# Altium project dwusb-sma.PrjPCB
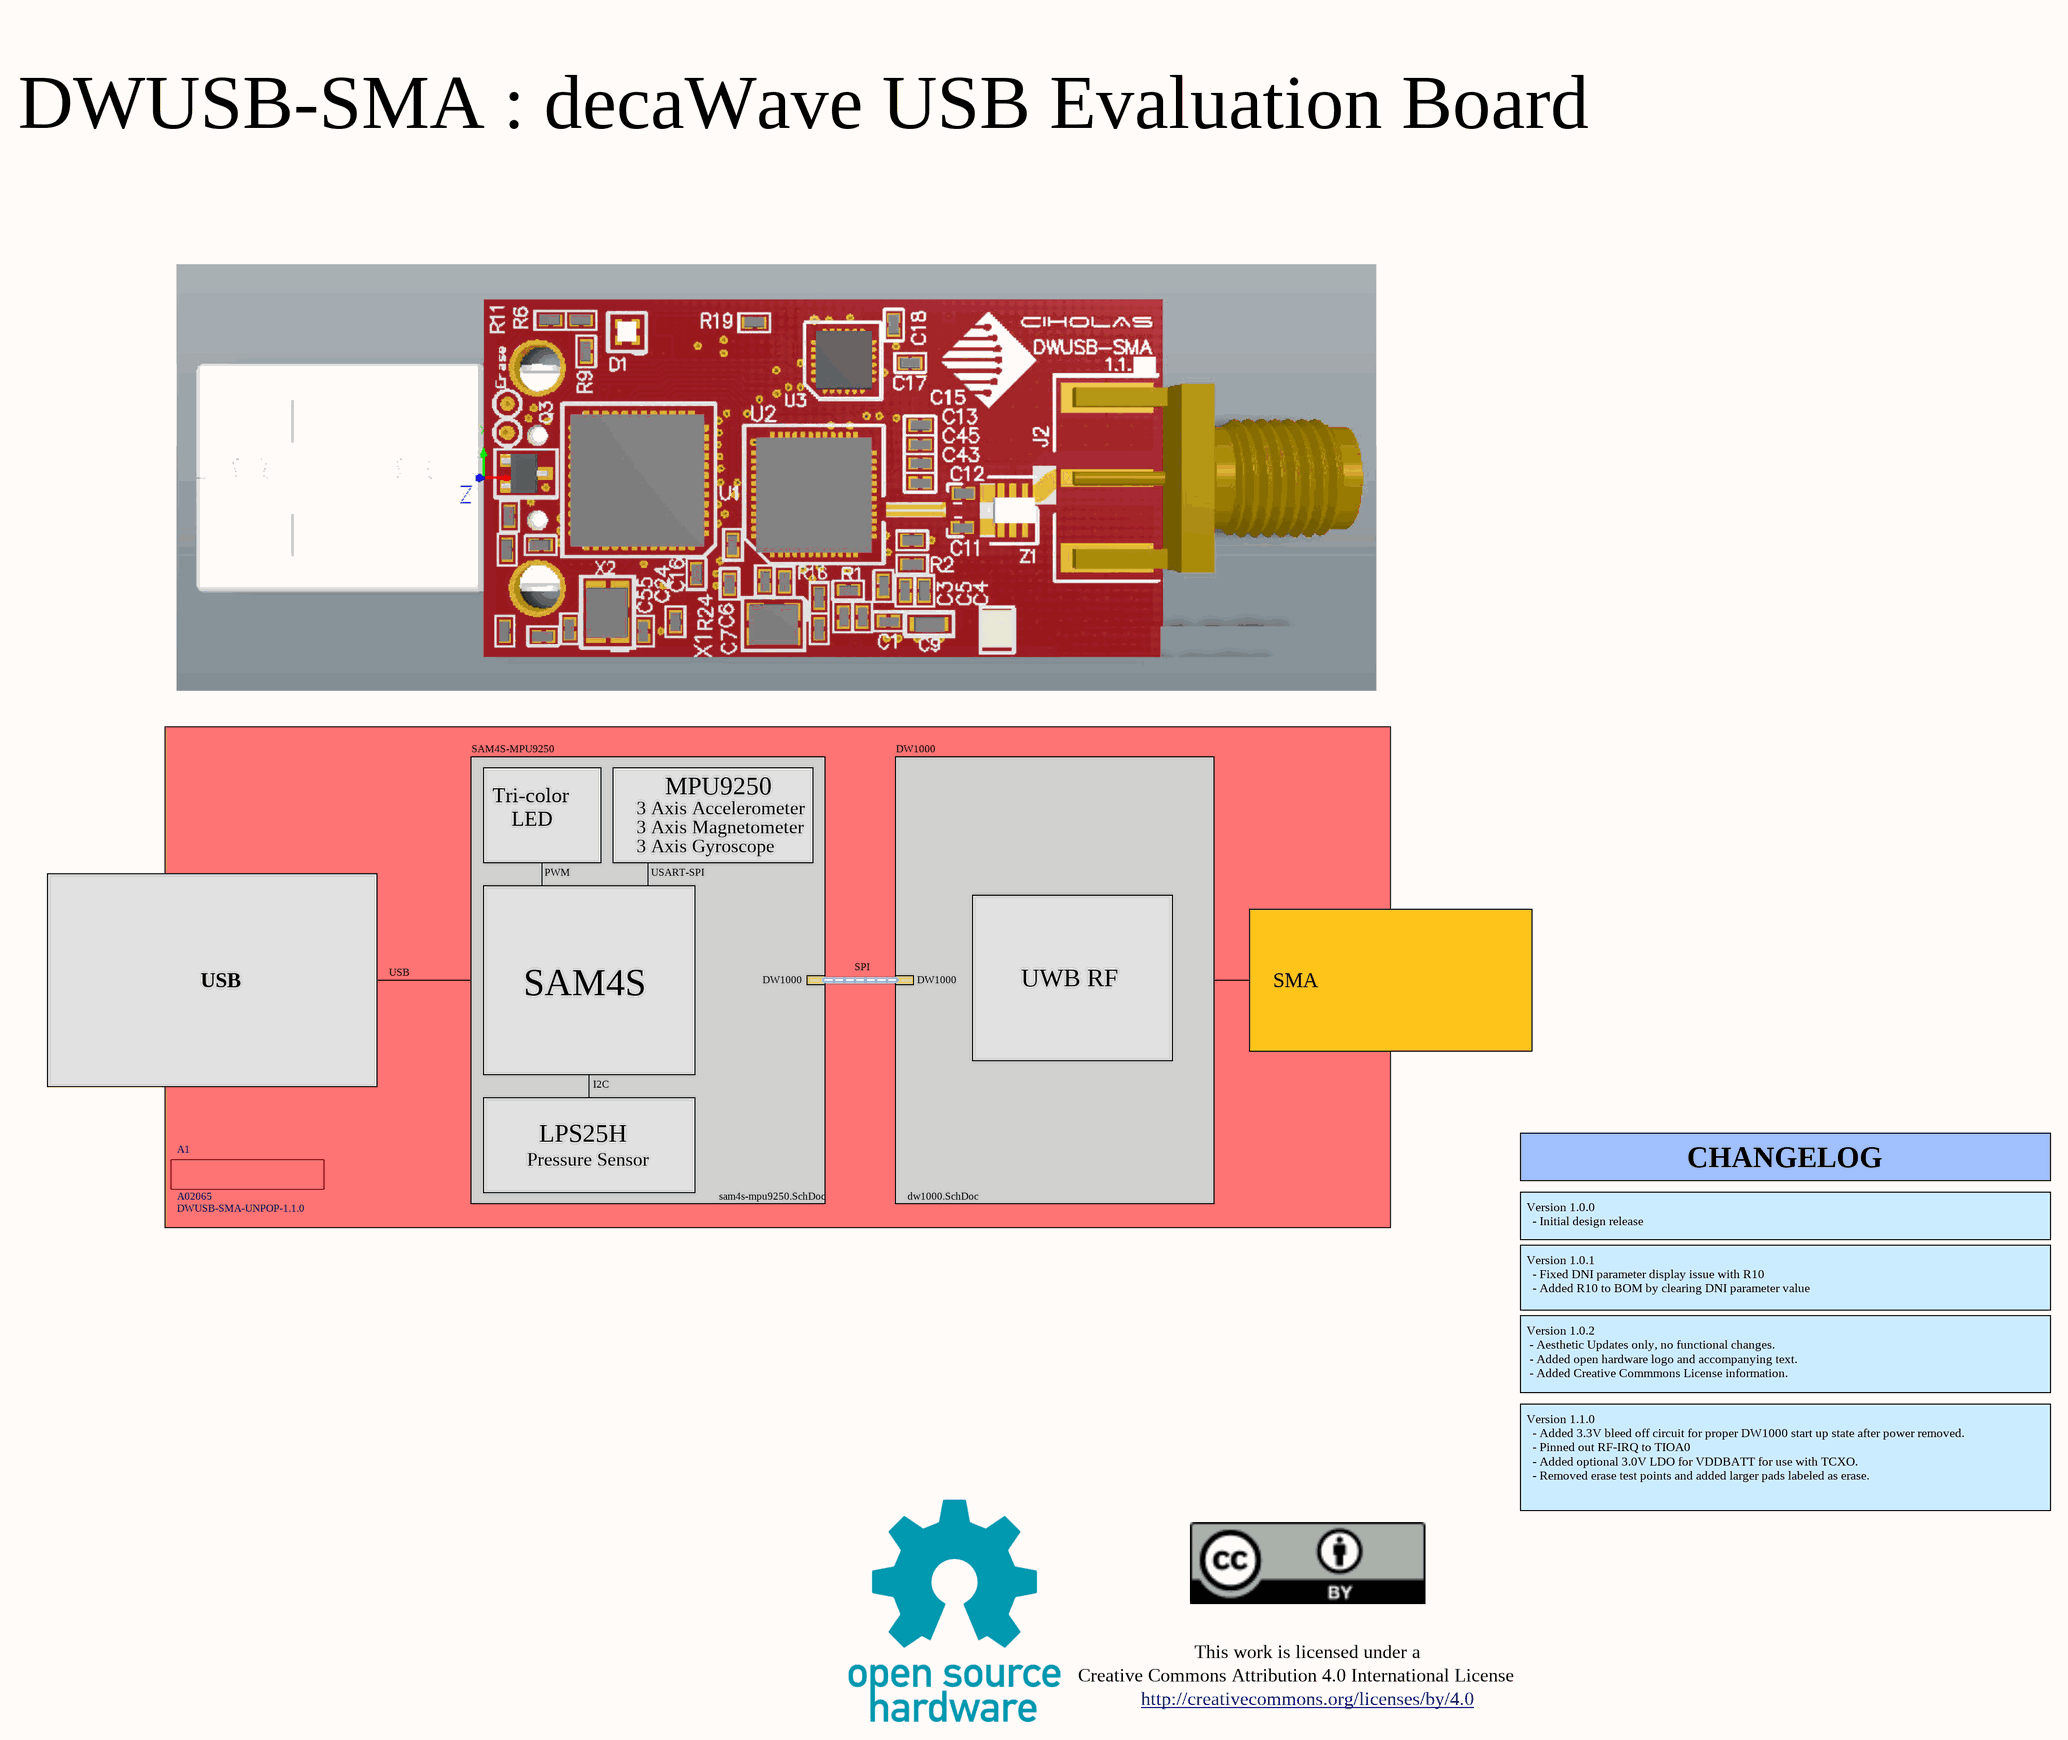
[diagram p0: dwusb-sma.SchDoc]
Client: Ciholas; Company Address1: 3700 Bell Rd; Company Address2: Newburgh, IN 47630; Email: gander@ciholas.com; Engineer: Chris Gander; PartNumber: DWUSB-SMA-UNPOP; Phone: (812)962-9410; ProjectRevision: 1.1.0; ProjectTitle: DWUSB-SMA
3 sheets, 104 parts. Net scope: hierarchical (ports join the sheet entries above them; power ports are global).
Board file: dwusb-sma.PcbDoc
Sheets:
  dwusb-sma.SchDoc
    SAM4S-MPU9250 = sam4s-mpu9250.SchDoc
    DW1000 = dw1000.SchDoc

## Sheet dwusb-sma.SchDoc
size 558 x 381 mm; Revision: 1.1; SheetNumber: 1; SheetTotal: 3; PageSetup: Record=PageOptions¦CenterHorizontal=True¦CenterVertical=True¦PrintScale=0.70¦XCorrection=1.00¦YCorrection=1.00¦PrintKind=1¦BorderSize=5000000¦LeftOffset=0¦BottomOffset=0¦Orientation=2¦PaperLength=1000¦PaperWidth=1000¦Scale=100¦PaperSource=257¦PrintQuality=600¦MediaType=1¦DitherType=10¦PrintScaleMode=1¦PaperKind=11x17¦PaperIndex=17; CopyrightYear: 2016

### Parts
A1  Part Number: DWUSB-SMA-UNPOP-1.1.0  CPN: A02065  [DG-270X100]  (hidden comment: A_DG-OUTLINE-DG-270X100)

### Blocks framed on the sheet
SAM4S: A1

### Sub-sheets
DW1000 = dw1000.SchDoc: DW1000 (harness DW1000)
SAM4S-MPU9250 = sam4s-mpu9250.SchDoc: DW1000 (harness DW1000)

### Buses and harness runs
harness sheet DW1000/DW1000 = sheet SAM4S-MPU9250/DW1000

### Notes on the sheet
- DWUSB-SMA : decaWave USB Evaluation Board
- Tri-color
- MPU9250
- LED
- 3 Axis Accelerometer
- 3 Axis Magnetometer
- 3 Axis Gyroscope
- PWM
- USART-SPI
- SPI
- USB
- UWB RF
- SMA
- I2C
- LPS25H
- Pressure Sensor
- CHANGELOG
- Version 1.0.0
  - Initial design release
- Version 1.0.1
  - Fixed DNI parameter display issue with R10
  - Added R10 to BOM by clearing DNI parameter value
- Version 1.0.2
  - Aesthetic Updates only, no functional changes.
  - Added open hardware logo and accompanying text.
  - Added Creative Commmons License information.
- Version 1.1.0
  - Added 3.3V bleed off circuit for proper DW1000 start up state after power removed.
  - Pinned out RF-IRQ to TIOA0
  - Added optional 3.0V LDO for VDDBATT for use with TCXO.
  - Removed erase test points and added larger pads labeled as erase.
- This work is licensed under a
- Creative Commons Attribution 4.0 International License
- http://creativecommons.org/licenses/by/4.0

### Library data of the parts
A1 = A02065: Ciholas Blank DWUSB SMA PCB Revision 1.1.0; Category Letter: A

## Sheet sam4s-mpu9250.SchDoc
size 558 x 381 mm; SheetNumber: 2; SheetTotal: 3; PageSetup: Record=PageOptions¦CenterHorizontal=True¦CenterVertical=True¦PrintScale=0.70¦XCorrection=1.00¦YCorrection=1.00¦PrintKind=1¦BorderSize=5000000¦LeftOffset=0¦BottomOffset=0¦Orientation=2¦PaperLength=1000¦PaperWidth=1000¦Scale=100¦PaperSource=257¦PrintQuality=600¦MediaType=1¦DitherType=10¦PrintScaleMode=1¦PaperKind=11x17¦PaperIndex=17; CopyrightYear: 2016
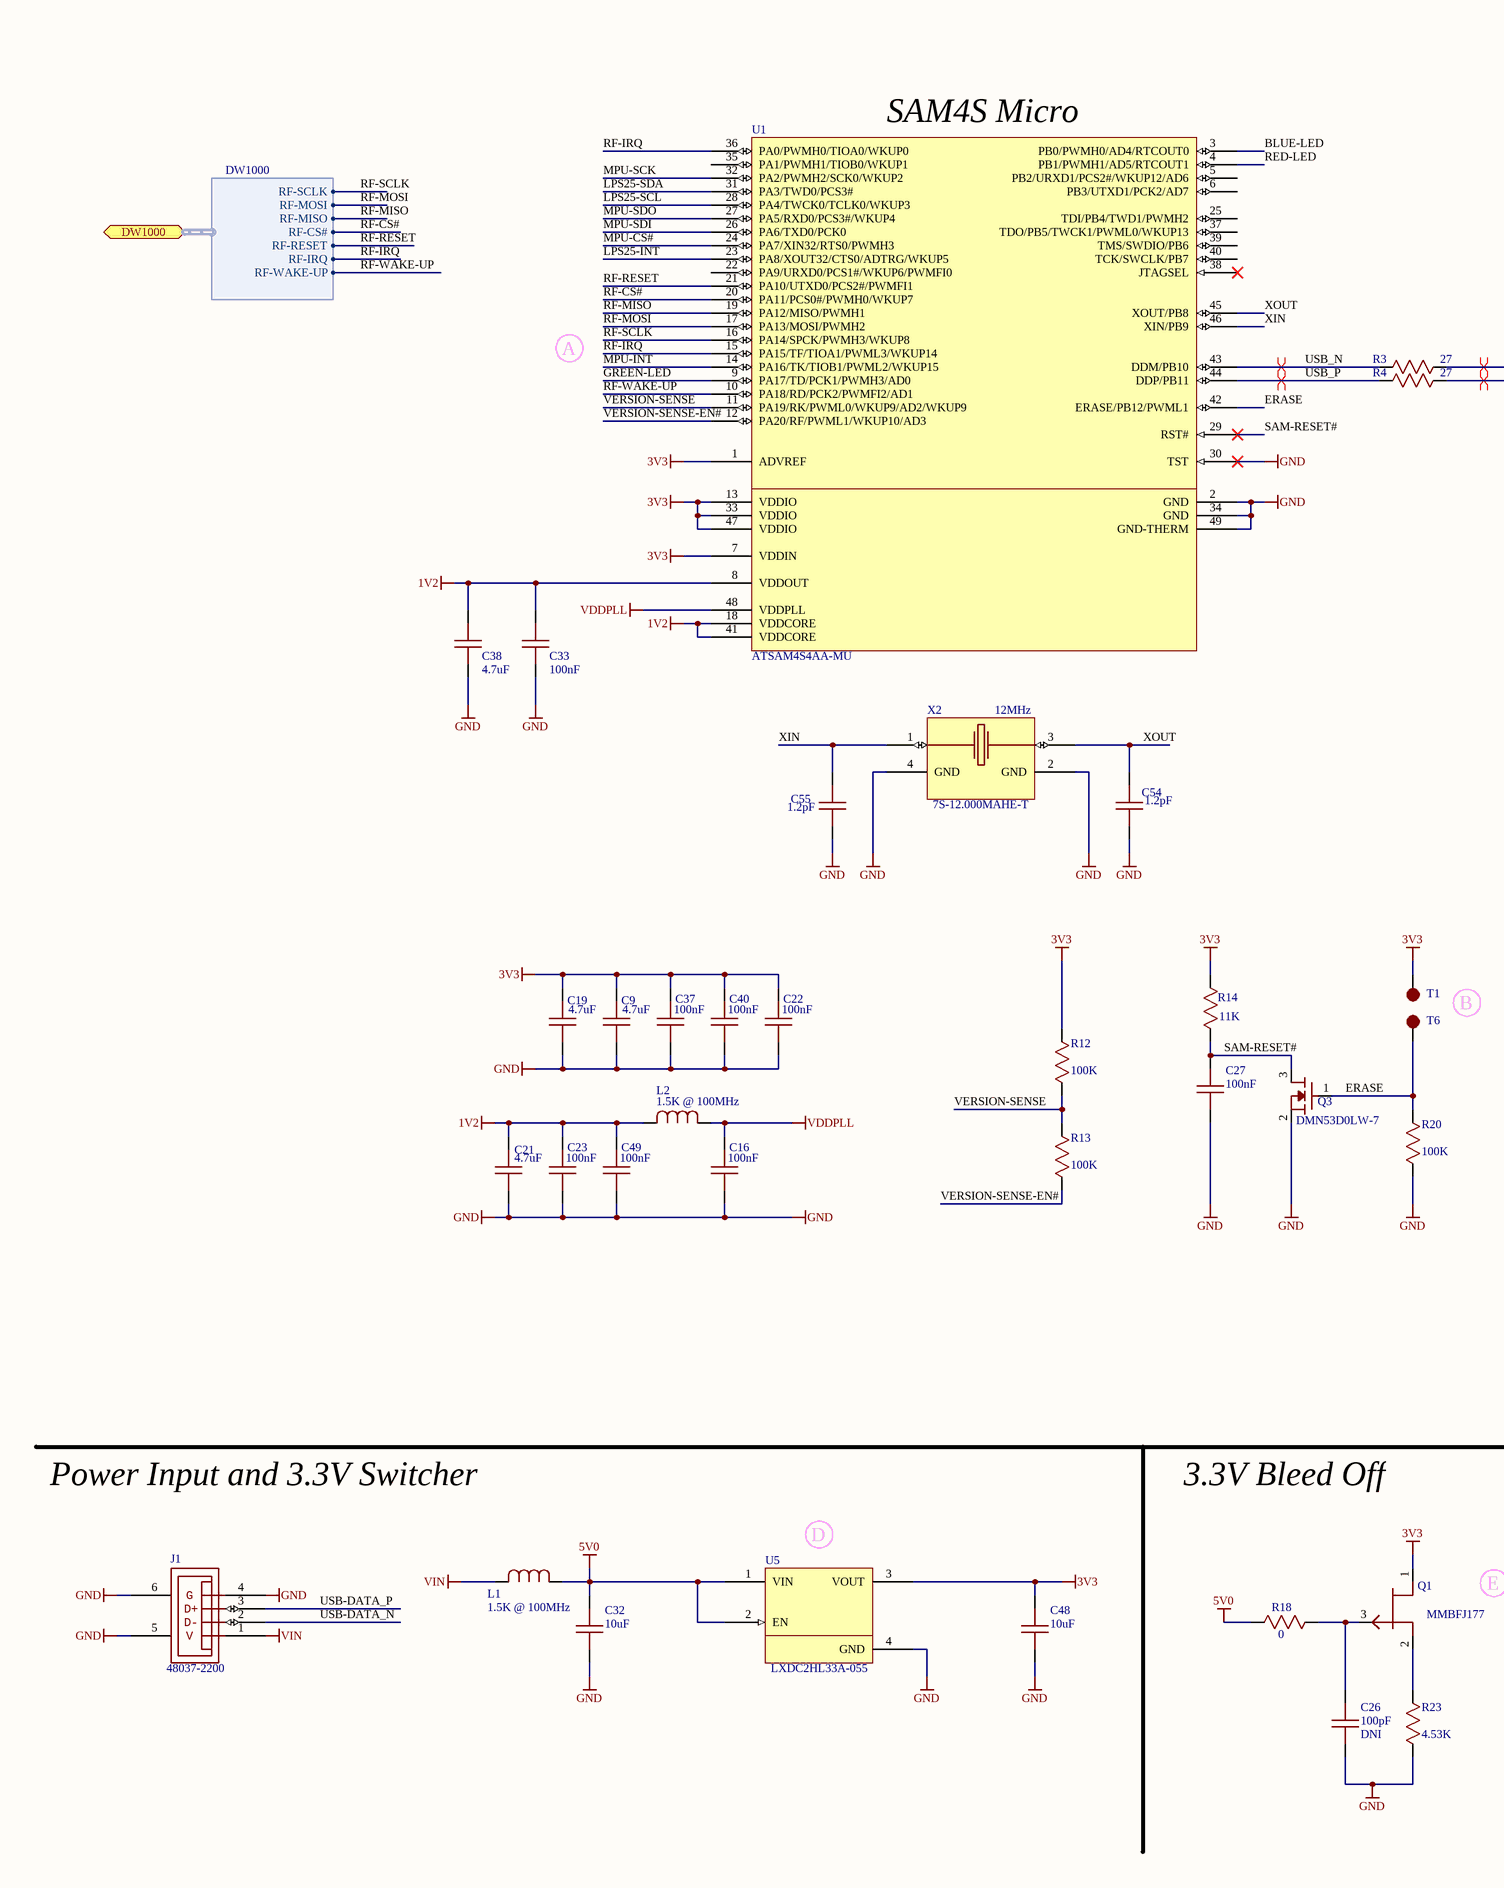
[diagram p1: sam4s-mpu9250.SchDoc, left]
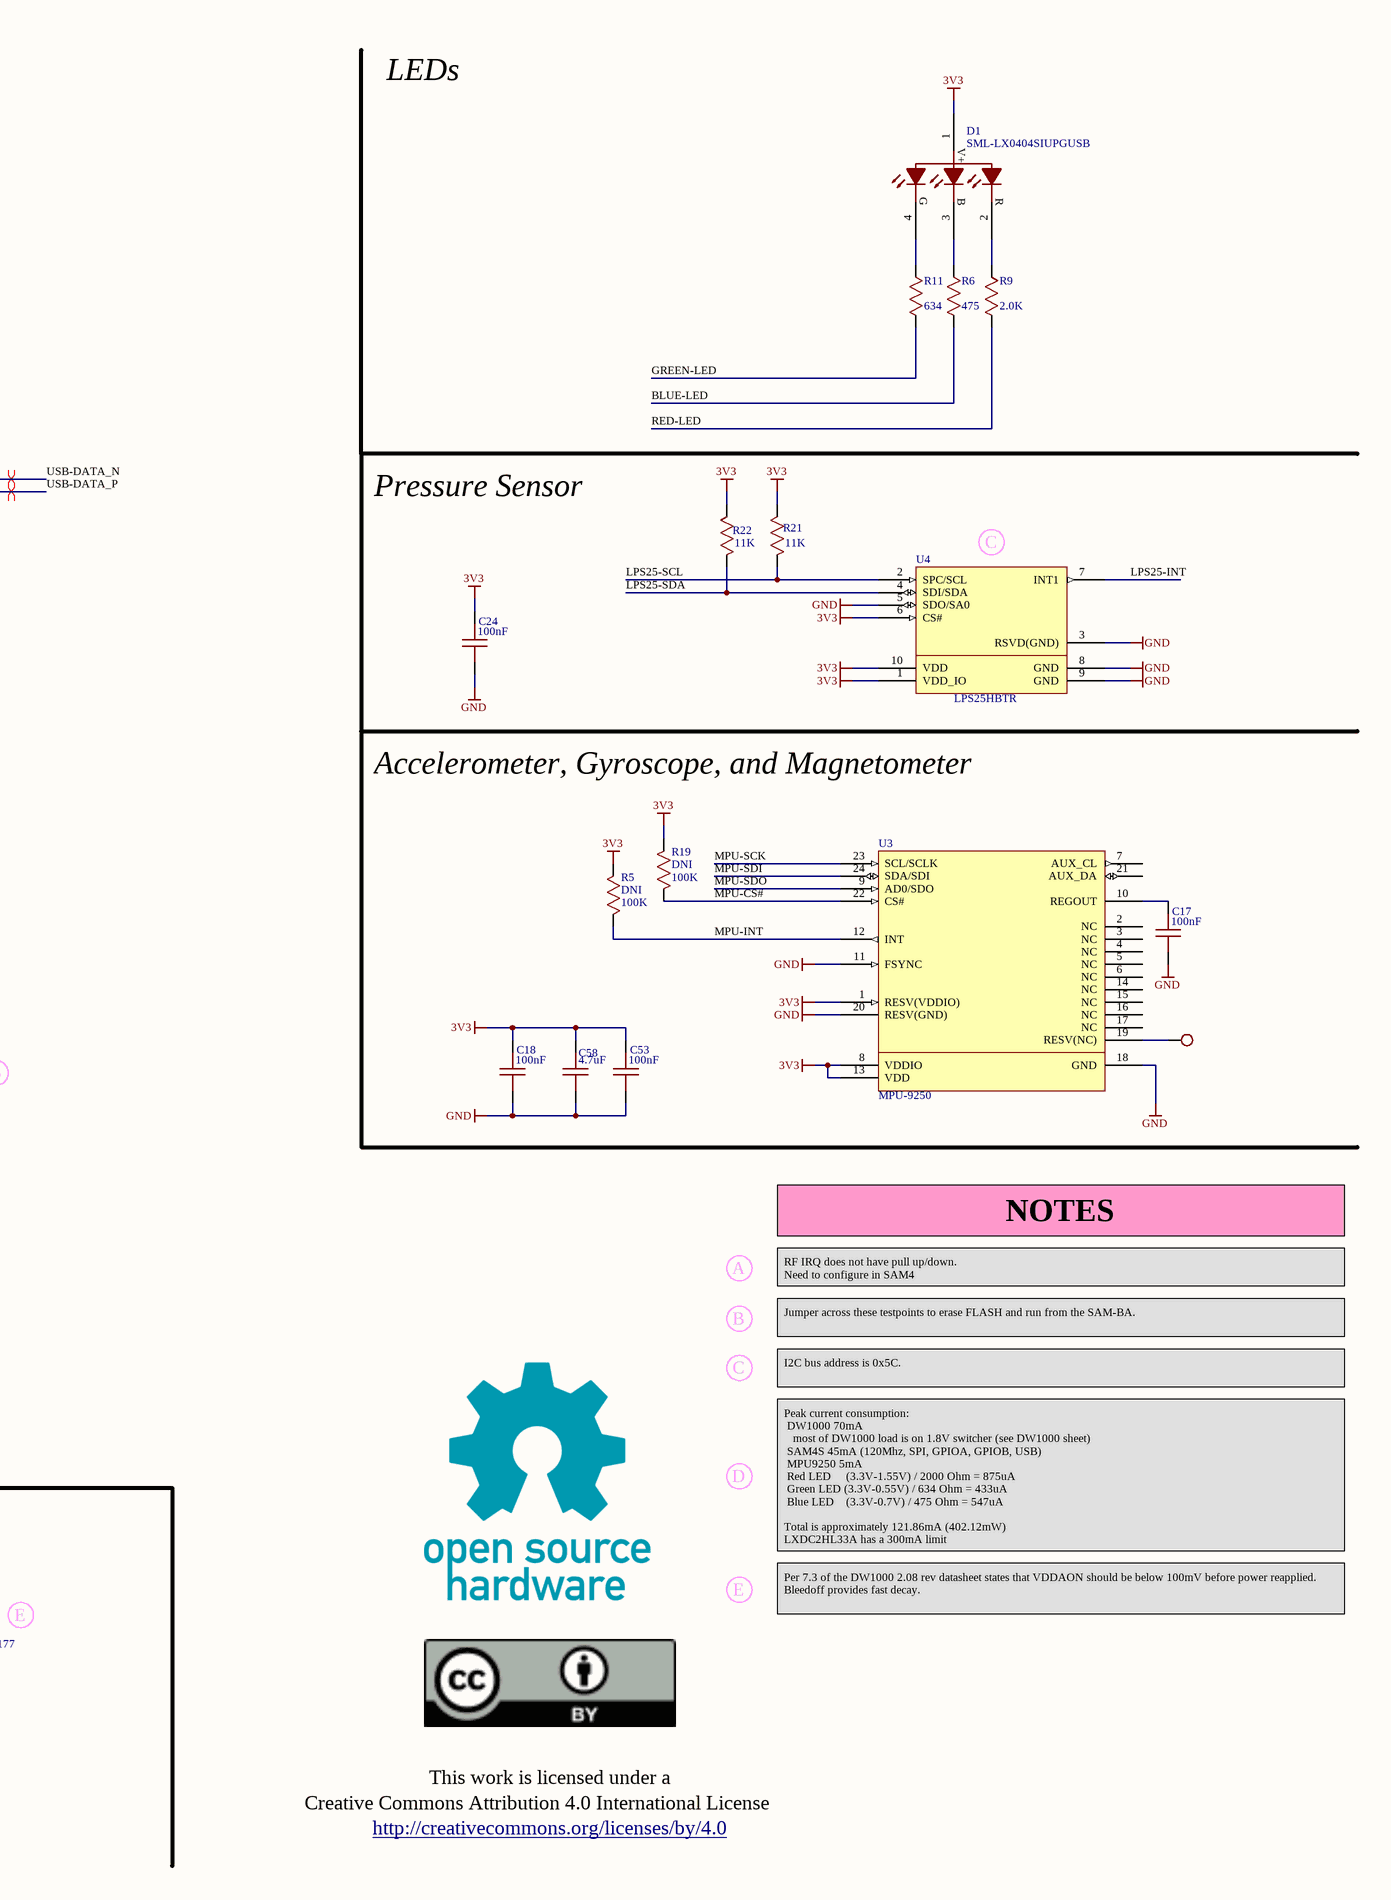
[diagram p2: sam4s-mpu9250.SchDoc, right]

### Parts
C9  value 4.7uF  [0603]  (hidden comment: C_CAP_0603)
C16  value 100nF  [0402]  (hidden comment: C_CAP_0402)
C17  value 100nF  [0402]  (hidden comment: C_CAP_0402)
C18  value 100nF  [0402]  (hidden comment: C_CAP_0402)
C19  value 4.7uF  [0603]  (hidden comment: C_CAP_0603)
C21  value 4.7uF  [0603]  (hidden comment: C_CAP_0603)
C22  value 100nF  [0402]  (hidden comment: C_CAP_0402)
C23  value 100nF  [0402]  (hidden comment: C_CAP_0402)
C24  value 100nF  [0402]  (hidden comment: C_CAP_0402)
C26  value 100pF  [0402]  (hidden comment: C_CAP_0402)
C27  value 100nF  [0402]  (hidden comment: C_CAP_0402)
C32  value 10uF  [0603]  (hidden comment: C_CAP_0603)
C33  value 100nF  [0402]  (hidden comment: C_CAP_0402)
C37  value 100nF  [0402]  (hidden comment: C_CAP_0402)
C38  value 4.7uF  [0603]  (hidden comment: C_CAP_0603)
C40  value 100nF  [0402]  (hidden comment: C_CAP_0402)
C48  value 10uF  [0603]  (hidden comment: C_CAP_0603)
C49  value 100nF  [0402]  (hidden comment: C_CAP_0402)
C53  value 100nF  [0402]  (hidden comment: C_CAP_0402)
C54  value 1.2pF  [0402]  (hidden comment: C_CAP_0402)
C55  value 1.2pF  [0402]  (hidden comment: C_CAP_0402)
C58  value 4.7uF  [0603]  (hidden comment: C_CAP_0603)
D1  Part Number: SML-LX0404SIUPGUSB  [0404-3C-LED]  (hidden comment: LED RGB SQUARE CLEAR SMD)
J1  J_USBA-PLUG_48037-2200  [48037-2200]  (value not drawn)
L1  value 1.5K @ 100MHz  [0603]  (hidden comment: L_IND_0603)
L2  value 1.5K @ 100MHz  [0603]  (hidden comment: L_IND_0603)
Q1  Part Number: MMBFJ177  [SOT23]  (hidden comment: Q_JFET-P_SOT23)
Q3  Part Number: DMN53D0LW-7  [SC70]  (hidden comment: Q00171)
R3  value 27  [0402]  (hidden comment: R_RES_0402)
R4  value 27  [0402]  (hidden comment: R_RES_0402)
R5  value 100K  [0402]  (hidden comment: R_RES_0402)
R6  value 475  [0402]  (hidden comment: R_RES_0402)
R9  value 2.0K  [0402]  (hidden comment: R_RES_0402)
R11  value 634  [0402]  (hidden comment: R_RES_0402)
R12  value 100K  [0402]  (hidden comment: R_RES_0402)
R13  value 100K  [0402]  (hidden comment: R_RES_0402)
R14  value 11K  [0402]  (hidden comment: R_RES_0402)
R18  value 0  [0402]  (hidden comment: R_RES_0402)
R19  value 100K  [0402]  (hidden comment: R_RES_0402)
R20  value 100K  [0402]  (hidden comment: R_RES_0402)
R21  value 11K  [0402]  (hidden comment: R_RES_0402)
R22  value 11K  [0402]  (hidden comment: R_RES_0402)
R23  value 4.53K  [0402]  (hidden comment: R_RES_0402)
T1  T_TESTPOINT-PAD_T31ES  [T31ES]  (value not drawn)
T4  T_TESTPOINT_H22D12EDS  [H22D12EDS]  (value not drawn)
T6  T_TESTPOINT-PAD_T31ES  [T31ES]  (value not drawn)
U1  Part Number: ATSAM4S4AA-MU  [QFN48]  (hidden comment: U00965)
U3  U00945  [MPU-9250]  (value not drawn)
U4  Part Number: LPS25HBTR  [LGA10-2M5]  (hidden comment: U01153)
U5  Part Number: LXDC2HL33A-055  [LXDC2HL]  (hidden comment: U_LXDC2HL_LXDC2HL)
X2  value 12MHz  Part Number: 7S-12.000MAHE-T  [ECX-2236]  (hidden comment: X_XTAL4P2G_ECX-2236)

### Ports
DW1000 (harness DW1000)

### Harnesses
DW1000: RF-SCLK, RF-MOSI, RF-MISO, RF-CS#, RF-IRQ, RF-WAKE-UP, RF-RESET

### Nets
1V2: C21.1 C23.1 C33.1 C38.1 C49.1 L2.1 U1.8(VDDOUT) U1.18(VDDCORE) U1.41(VDDCORE)
3V3: C9.1 C18.1 C19.1 C22.1 C24.1 C37.1 C40.1 C48.1 C53.1 C58.1 D1.1(V+) Q1.1(D) R5.2 R12.2 R14.2 R19.2 R21.2 R22.2 T1.1 U1.1(ADVREF) U1.7(VDDIN) U1.13(VDDIO) U1.33(VDDIO) U1.47(VDDIO) U3.1(RESV(VDDIO)) U3.8(VDDIO) U3.13(VDD) U4.1(VDD_IO) U4.6(CS#) U4.10(VDD) U5.3(VOUT)
5V0: C32.1 L1.2 R18.1 U5.1(VIN) U5.2(EN)
GND: C9.2 C16.2 C17.2 C18.2 C19.2 C21.2 C22.2 C23.2 C24.2 C26.2 C27.2 C32.2 C33.2 C37.2 C38.2 C40.2 C48.2 C49.2 C53.2 C54.2 C55.2 C58.2 J1.4(GND) J1.5(SHIELD) J1.6(SHIELD) Q3.2(S) R20.1 R23.1 U1.2(GND) U1.30(TST) U1.34(GND) U1.49(GND-THERM) U3.11(FSYNC) U3.18(GND) U3.20(RESV(GND)) U4.3(RSVD(GND)) U4.5(SDO/SA0) U4.8(GND) U4.9(GND) U5.4(GND) X2.2(GND) X2.4(GND)
VDDPLL: C16.1 L2.2 U1.48(VDDPLL)
VIN: J1.1(+5V) L1.1
BLUE-LED: R6.1 U1.3(PB0/PWMH0/AD4/RTCOUT0)
ERASE: Q3.1(G) R20.2 T6.1 U1.42(ERASE/PB12/PWML1)
GREEN-LED: R11.1 U1.9(PA17/TD/PCK1/PWMH3/AD0)
LPS25-INT: U1.23(PA8/XOUT32/CTS0/ADTRG/WKUP5) U4.7(INT1)
LPS25-SCL: R21.1 U1.28(PA4/TWCK0/TCLK0/WKUP3) U4.2(SPC/SCL)
LPS25-SDA: R22.1 U1.31(PA3/TWD0/PCS3#) U4.4(SDI/SDA)
MPU-CS#: R19.1 U1.24(PA7/XIN32/RTS0/PWMH3) U3.22(CS#)
MPU-INT: R5.1 U1.14(PA16/TK/TIOB1/PWML2/WKUP15) U3.12(INT)
MPU-SCK: U1.32(PA2/PWMH2/SCK0/WKUP2) U3.23(SCL/SCLK)
MPU-SDI: U1.26(PA6/TXD0/PCK0) U3.24(SDA/SDI)
MPU-SDO: U1.27(PA5/RXD0/PCS3#/WKUP4) U3.9(AD0/SDO)
RED-LED: R9.1 U1.4(PB1/PWMH1/AD5/RTCOUT1)
RF-CS#: U1.20(PA11/PCS0#/PWMH0/WKUP7) ; port DW1000.RF-CS#
RF-IRQ: U1.15(PA15/TF/TIOA1/PWML3/WKUP14) U1.36(PA0/PWMH0/TIOA0/WKUP0) ; port DW1000.RF-IRQ
RF-MISO: U1.19(PA12/MISO/PWMH1) ; port DW1000.RF-MISO
RF-MOSI: U1.17(PA13/MOSI/PWMH2) ; port DW1000.RF-MOSI
RF-RESET: U1.21(PA10/UTXD0/PCS2#/PWMFI1) ; port DW1000.RF-RESET
RF-SCLK: U1.16(PA14/SPCK/PWMH3/WKUP8) ; port DW1000.RF-SCLK
RF-WAKE-UP: U1.10(PA18/RD/PCK2/PWMFI2/AD1) ; port DW1000.RF-WAKE-UP
SAM-RESET#: C27.1 Q3.3(D) R14.1 U1.29(RST#)
USB-DATA_N: J1.2(-DATA) R3.2
USB-DATA_P: J1.3(+DATA) R4.2
USB_N: R3.1 U1.43(DDM/PB10)
USB_P: R4.1 U1.44(DDP/PB11)
VERSION-SENSE: R12.1 R13.2 U1.11(PA19/RK/PWML0/WKUP9/AD2/WKUP9)
VERSION-SENSE-EN#: R13.1 U1.12(PA20/RF/PWML1/WKUP10/AD3)
XIN: C55.1 U1.46(XIN/PB9) X2.1(X1)
XOUT: C54.1 U1.45(XOUT/PB8) X2.3(X2)
NetC17_1: C17.1 U3.10(REGOUT)
NetC26_1: C26.1 Q1.3(G) R18.2
NetD1_2: D1.2(R) R9.2
NetD1_3: D1.3(B) R6.2
NetD1_4: D1.4(G) R11.2
NetQ1_2: Q1.2(S) R23.2
NetT4_1: T4.1 U3.19(RESV(NC))

Not connected (* = marked no-connect by the designer): U1 5(PB2/URXD1/PCS2#/WKUP12/AD6) 6(PB3/UTXD1/PCK2/AD7) 22(PA9/URXD0/PCS1#/WKUP6/PWMFI0) 25(TDI/PB4/TWD1/PWMH2) 35(PA1/PWMH1/TIOB0/WKUP1) 37(TDO/PB5/TWCK1/PWML0/WKUP13) 38(JTAGSEL)* 39(TMS/SWDIO/PB6) 40(TCK/SWCLK/PB7); U3 2(NC) 3(NC) 4(NC) 5(NC) 6(NC) 7(AUX_CL) 14(NC) 15(NC) 16(NC) 17(NC) 21(AUX_DA)

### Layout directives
differential pair: USB-DATA_N, USB-DATA_P, USB_N, USB_P

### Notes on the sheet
- LEDs
- (near U1) SAM4S Micro
- A
- Pressure Sensor
- (near U4) C
- Accelerometer, Gyroscope, and Magnetometer
- B
- NOTES
- RF IRQ does not have pull up/down.
  Need to configure in SAM4
- Jumper across these testpoints to erase FLASH and run from the SAM-BA.
- C
- I2C bus address is 0x5C.
- D
- Power Input and 3.3V Switcher
- 3.3V Bleed Off
- Peak current consumption:
  DW1000 70mA
  most of DW1000 load is on 1.8V switcher (see DW1000 sheet)
  SAM4S 45mA (120Mhz, SPI, GPIOA, GPIOB, USB)
  MPU9250 5mA
  Red LED     (3.3V-1.55V) / 2000 Ohm = 875uA
  Green LED (3.3V-0.55V) / 634 Ohm = 433uA
  Blue LED    (3.3V-0.7V) / 475 Ohm = 547uA
  Total is approximately 121.86mA (402.12mW)
  LXDC2HL33A has a 300mA limit
- (near U5) D
- E
- Per 7.3 of the DW1000 2.08 rev datasheet states that VDDAON should be below 100mV before power reapplied.
  Bleedoff provides fast decay.
- This work is licensed under a
- Creative Commons Attribution 4.0 International License
- http://creativecommons.org/licenses/by/4.0

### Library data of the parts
C9 C19 C21 C58 = C00213: Part Number: GRM188F51A475ZE20D; CPN: C00213; Rating: 10V; Tolerance: +80/-20%; Title: Capacitor 4.7uF 10V Ceramic Y5V 0603; Category Letter: C
C16-C18 C22-C24 C27 C33 C37 C40 C49 C53 = C00136: Capacitor 100nF 10V Ceramic X5R 0402; Part Number: GRM155R61A104KA01D; CPN: C00136; Tolerance: +/-10%; Category Letter: C
C26 = C00434: CAP CER 100PF 50V 5% NP0 0402; Part Number: C1005C0G1H101J050BA; CPN: C00434; Category Letter: C
C32 = C00431: CAP CER 10UF 16V 20% X5R 0603; Part Number: C1608X5R1C106M080AB; CPN: C00431; Category Letter: C
C38 = C00213: Capacitor 4.7uF 10V Ceramic Y5V 0603; Part Number: GRM188F51A475ZE20D; CPN: C00213; Tolerance: +80/-20%; Category Letter: C
C48 = C00171: Capacitor 10uF 6.3V Ceramic X5R 0603; Part Number: C0603C106M9PACTU; CPN: C00171; Tolerance: 20%; Category Letter: C
C54 C55 = C00458: Ceramic Capacitor 0402 1.2pF NP0; Part Number: GRM1555C1H1R2WA01D; CPN: C00458; Rating: 50V; Tolerance: Â±0.05pF; Category Letter: C
D1 = D00360: CPN: D00360; Category Letter: D
J1 = J01292: USB Connectors A Type SMT; CPN: J01292; Category Letter: J
L1 L2 = L00246: Ferrite Bead 1.5k@100Mhz SMD 0603 500mA; Part Number: BLM18HE152SN1D; CPN: L00246; Rating: 500mA 500mOhm; Category Letter: L
Q1 = Q_JFET-P_SOT23: CPN: Q00084; Title: JFET P-Channel 30V SOT-23; Category Letter: Q
Q3 = Q00171: MOSFET N-CH 50V 360mA SC70-3; Category Letter: Q
R3 R4 = R00714: RES 27 OHM 1/10W 1% 0402 SMD; Part Number: ERJ-2RKF27R0X; CPN: R00714; Tolerance: Â±1%; Category Letter: R
R5 R12 R13 R19 R20 = R00696: RES 100K OHM 1/16W 1% 0402 SMD; Part Number: MCR01MRTF1003; CPN: R00696; Tolerance: +/-1%; Category Letter: R
R6 = R00726: RES 475 OHM 1/10W 1% 0402 SMD; Part Number: ERJ-2RKF4750X; CPN: R00726; Category Letter: R
R9 = R00698: RES 2.00K OHM 1/10W 1% 0402 SMD; Part Number: ERJ-2RKF2001X; CPN: R00698; Category Letter: R
R11 = R00547: RES 634 OHM 1/16W 1% 0402 SMD; Part Number: RMCF0402FT634R; CPN: R00547; Tolerance: Â±1%; Category Letter: R
R14 R21 R22 = R00704: RES 11K OHM 1/10W 1% 0402 SMD; Part Number: ERJ-2RKF1102X; CPN: R00704; Rating: 0.1W; Category Letter: R
R18 = R00661: Resistor 0 ohm 1/16W 5% 0402 SMD; Part Number: AC0402JR-070RL; CPN: R00661; Tolerance: +/- 5%; Category Letter: R
R23 = R00784: RES 4.53K OHM 1/10W 1% 0402 SMD; Part Number: ERJ-2RKF4531X; CPN: R00784; Rating: 0.1W; Category Letter: R
T1 T6 = T00003: CPN: T00003
T4 = T00015: Test Point 0.012" diameter hole with 0.022" diameter pad; CPN: T00015; Category Letter: T
U1 = U00965: Atmel ATSAM4S Series MCU 48-Pin QFN; Category Letter: U
U3 = U00945: 9-AXIS MEMS ACCELEROMTER/GYROSCOPE/MAG; Category Letter: U
U4 = U01153: IC PRESSURE SENSOR 260-1260 hPa SMD LGA10-2M5; Category Letter: U; Rating: 260 hPA - 1260 hPa; Tolerance: +/- 2 C
U5 = U01049: DC/DC Converter 3.3V 300MA SMD; CPN: U01049; Category Letter: U
X2 = X00141: Crystal 12MHz 12pF SMD; CPN: X00141; Tolerance: +/-30ppm; Category Letter: X

## Sheet dw1000.SchDoc
size 558 x 381 mm; SheetNumber: 3; SheetTotal: 3; PageSetup: Record=PageOptions¦CenterHorizontal=True¦CenterVertical=True¦PrintScale=0.70¦XCorrection=1.00¦YCorrection=1.00¦PrintKind=1¦BorderSize=5000000¦LeftOffset=0¦BottomOffset=0¦Orientation=2¦PaperLength=1000¦PaperWidth=1000¦Scale=100¦PaperSource=257¦PrintQuality=600¦MediaType=1¦DitherType=10¦PrintScaleMode=1¦PaperKind=11x17¦PaperIndex=17; CopyrightYear: 2016
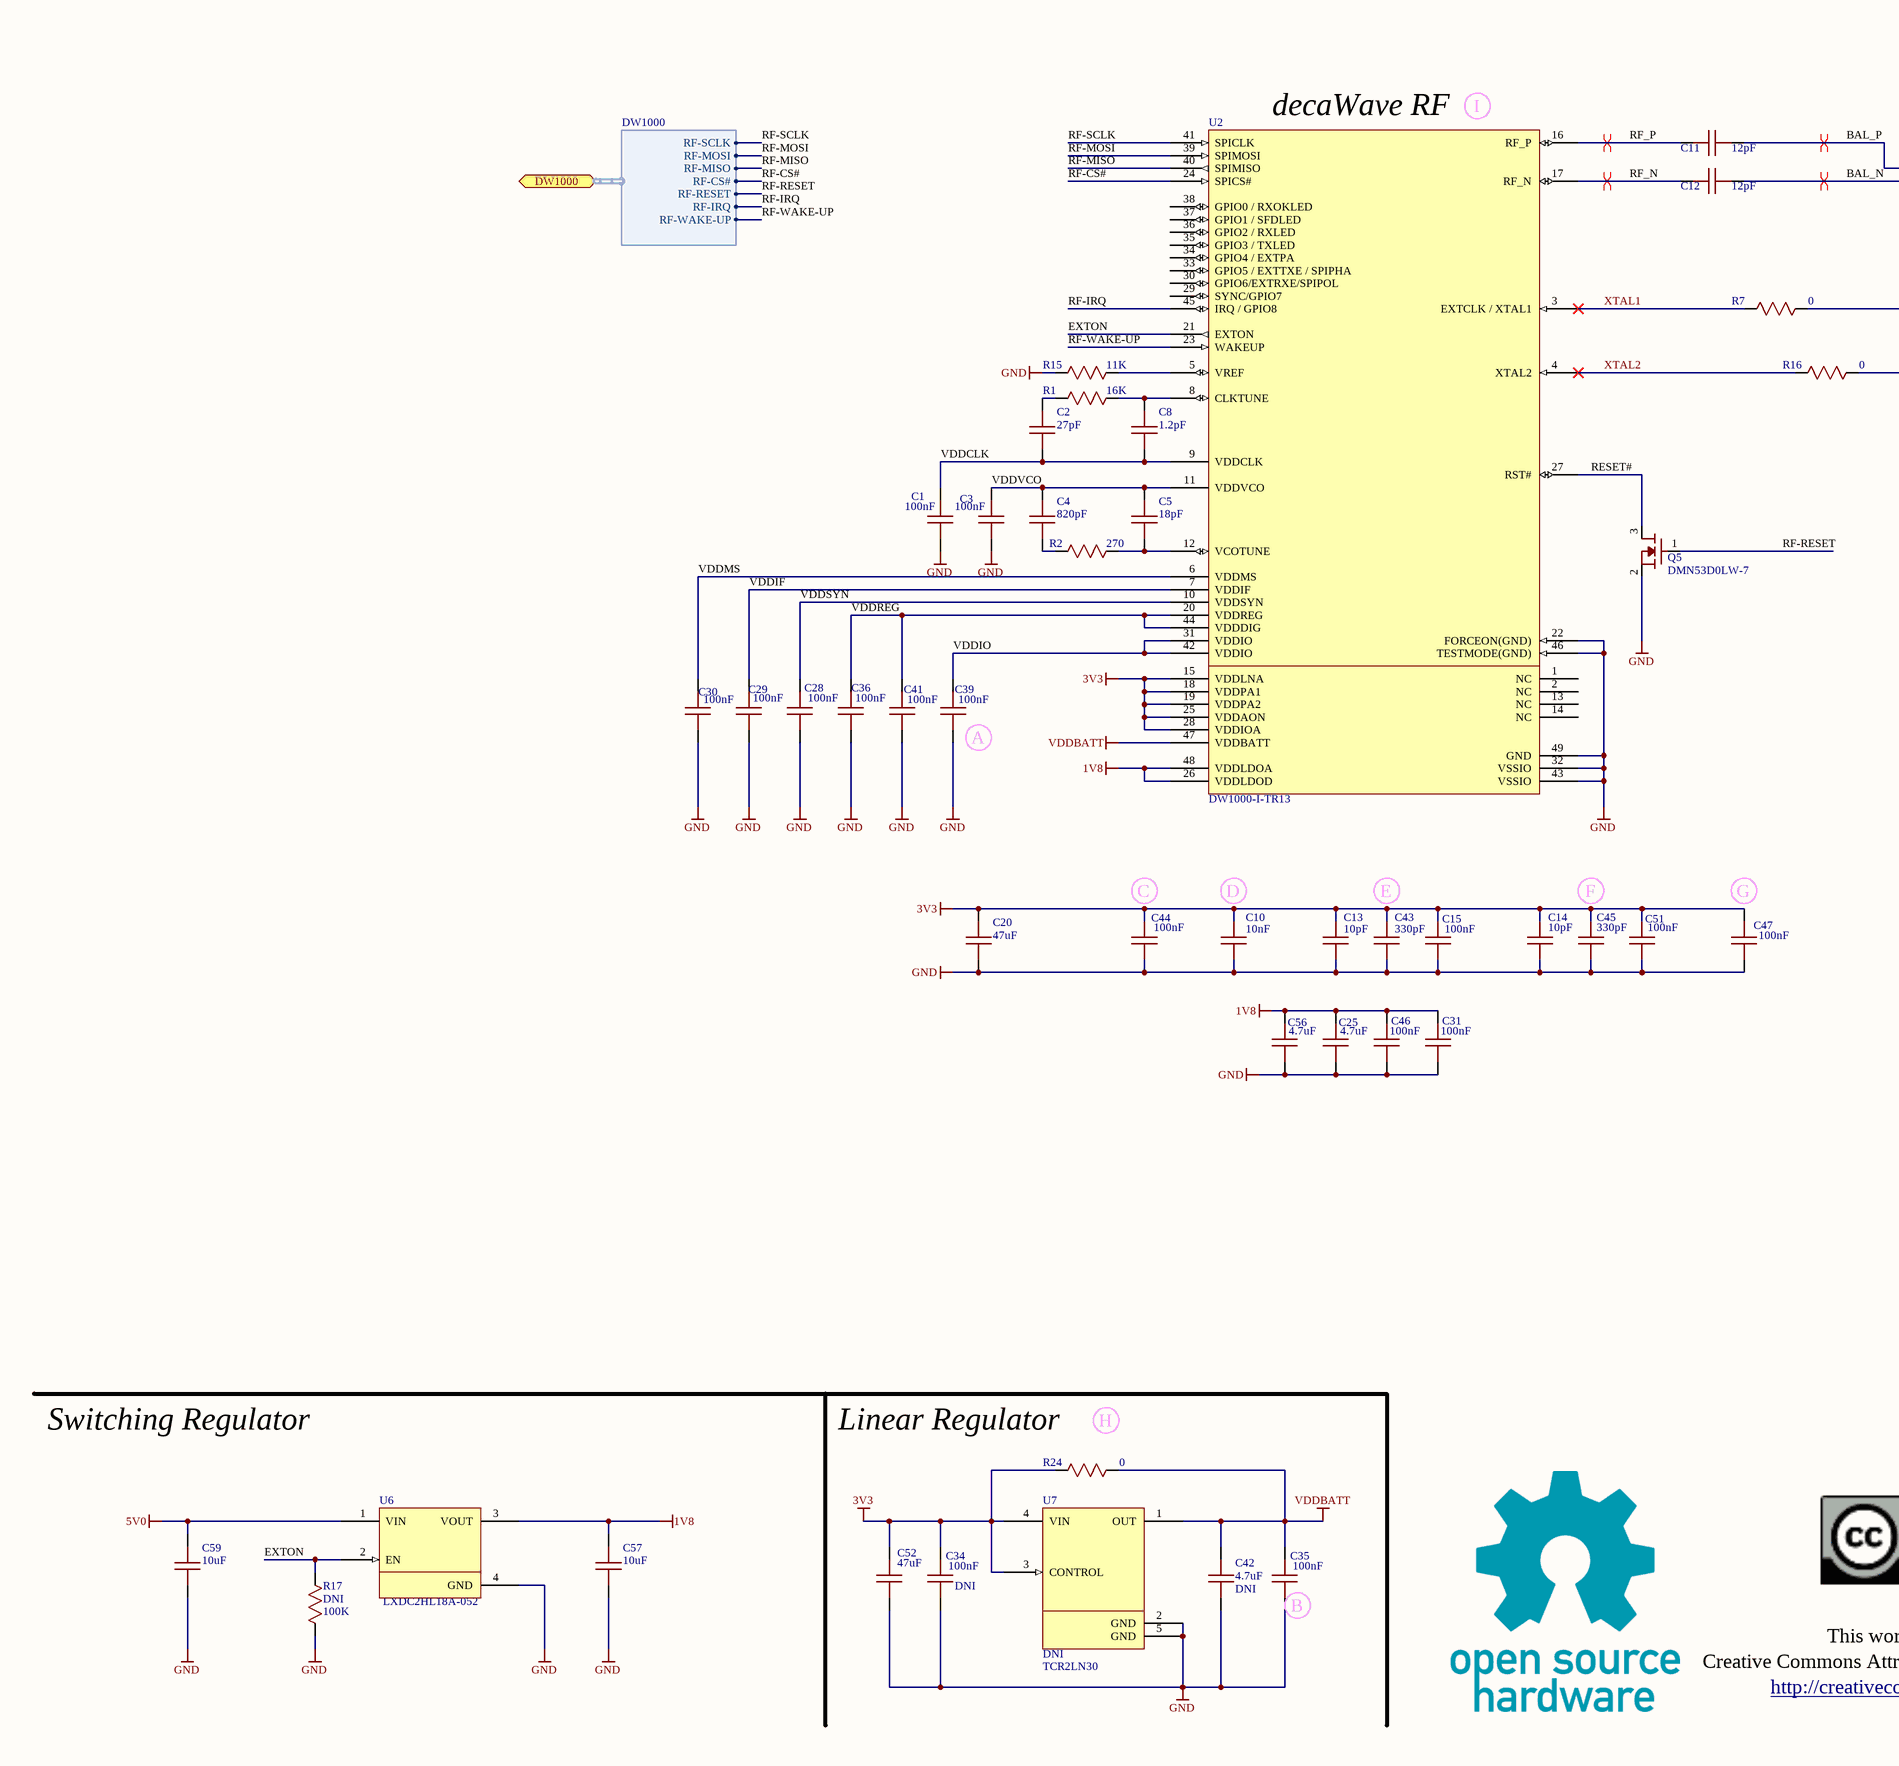
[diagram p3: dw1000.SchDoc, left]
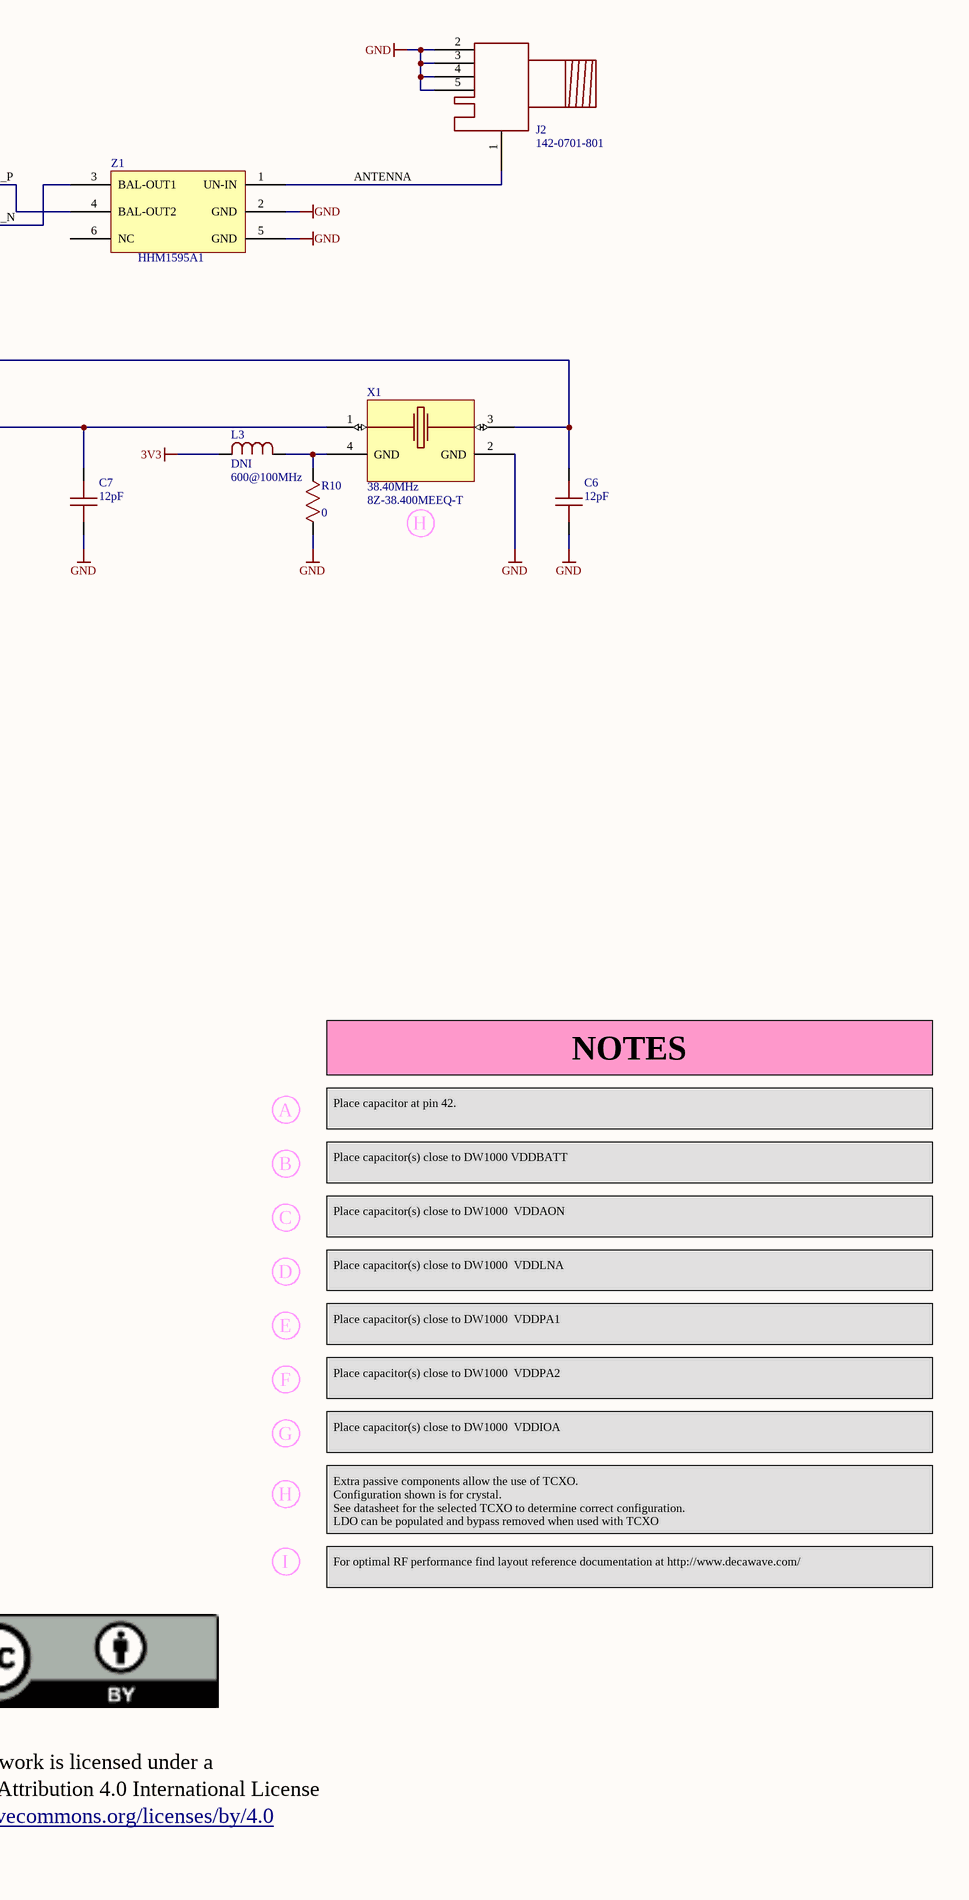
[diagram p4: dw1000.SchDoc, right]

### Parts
C1  value 100nF  [0402]  (hidden comment: C_CAP_0402)
C2  value 27pF  [0402]  (hidden comment: C_CAP_0402)
C3  value 100nF  [0402]  (hidden comment: C_CAP_0402)
C4  value 820pF  [0402]  (hidden comment: C_CAP_0402)
C5  value 18pF  [0402]  (hidden comment: C_CAP_0402)
C6  value 12pF  [0402]  (hidden comment: C_CAP_0402)
C7  value 12pF  [0402]  (hidden comment: C_CAP_0402)
C8  value 1.2pF  [0402]  (hidden comment: C_CAP_0402)
C10  value 10nF  [0402]  (hidden comment: C_CAP_0402)
C11  value 12pF  [0402]  (hidden comment: C_CAP_0402)
C12  value 12pF  [0402]  (hidden comment: C_CAP_0402)
C13  value 10pF  [0402]  (hidden comment: C_CAP_0402)
C14  value 10pF  [0402]  (hidden comment: C_CAP_0402)
C15  value 100nF  [0402]  (hidden comment: C_CAP_0402)
C20  value 47uF  [0805]  (hidden comment: C_CAP_0805)
C25  value 4.7uF  [0603]  (hidden comment: C_CAP_0603)
C28  value 100nF  [0402]  (hidden comment: C_CAP_0402)
C29  value 100nF  [0402]  (hidden comment: C_CAP_0402)
C30  value 100nF  [0402]  (hidden comment: C_CAP_0402)
C31  value 100nF  [0402]  (hidden comment: C_CAP_0402)
C34  value 100nF  [0402]  (hidden comment: C_CAP_0402)
C35  value 100nF  [0402]  (hidden comment: C_CAP_0402)
C36  value 100nF  [0402]  (hidden comment: C_CAP_0402)
C39  value 100nF  [0402]  (hidden comment: C_CAP_0402)
C41  value 100nF  [0402]  (hidden comment: C_CAP_0402)
C42  value 4.7uF  [0402]  (hidden comment: C_CAP_0402)
C43  value 330pF  [0402]  (hidden comment: C_CAP_0402)
C44  value 100nF  [0402]  (hidden comment: C_CAP_0402)
C45  value 330pF  [0402]  (hidden comment: C_CAP_0402)
C46  value 100nF  [0402]  (hidden comment: C_CAP_0402)
C47  value 100nF  [0402]  (hidden comment: C_CAP_0402)
C51  value 100nF  [0402]  (hidden comment: C_CAP_0402)
C52  value 47uF  [0805]  (hidden comment: C_CAP_0805)
C56  value 4.7uF  [0603]  (hidden comment: C_CAP_0603)
C57  value 10uF  [0603]  (hidden comment: C_CAP_0603)
C59  value 10uF  [0603]  (hidden comment: C_CAP_0603)
J2  J01340  [142-0701-801]  (value not drawn)
L3  value 600@100MHz  [0402]  (hidden comment: L_IND_0402)
Q5  Part Number: DMN53D0LW-7  [SC70]  (hidden comment: Q00171)
R1  value 16K  [0402]  (hidden comment: R_RES_0402)
R2  value 270  [0402]  (hidden comment: R_RES_0402)
R7  value 0  [0402]  (hidden comment: R_RES_0402)
R10  value 0  [0402]  (hidden comment: R_RES_0402)
R15  value 11K  [0402]  (hidden comment: R_RES_0402)
R16  value 0  [0402]  (hidden comment: R_RES_0402)
R17  value 100K  [0402]  (hidden comment: R_RES_0402)
R24  value 0  [0402]  (hidden comment: R_RES_0402)
U2  Part Number: DW1000-I-TR13  [QFN48-6M0]  (hidden comment: U00956)
U6  Part Number: LXDC2HL18A-052  [LXDC2HL]  (hidden comment: U00987)
U7  Part Number: TCR2LN30  [SDFN4]  (hidden comment: U_TCR2LN_SDFN4)
X1  value 38.40MHz  Part Number: 8Z-38.400MEEQ-T  [7Z-2M0X1M6-4P]  (hidden comment: X_XTAL4P2G_ECX-2236)
Z1  Part Number: HHM1595A1  [0805-6]  (hidden comment: Z_WE-BAL_0805-6)

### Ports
DW1000 (harness DW1000)

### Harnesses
DW1000: RF-SCLK, RF-MOSI, RF-MISO, RF-CS#, RF-IRQ, RF-WAKE-UP, RF-RESET

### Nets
1V8: C25.1 C31.1 C46.1 C56.1 C57.1 U2.26(VDDLDOD) U2.48(VDDLDOA) U6.3(VOUT)
3V3: C10.1 C13.1 C14.1 C15.1 C20.1 C34.1 C43.1 C44.1 C45.1 C47.1 C51.1 C52.1 L3.1 R24.1 U2.15(VDDLNA) U2.18(VDDPA1) U2.19(VDDPA2) U2.25(VDDAON) U2.28(VDDIOA) U7.3(CONTROL) U7.4(VIN)
5V0: C59.1 U6.1(VIN)
GND: C1.1 C3.2 C6.1 C7.1 C10.2 C13.2 C14.2 C15.2 C20.2 C25.2 C28.2 C29.2 C30.2 C31.2 C34.2 C35.2 C36.2 C39.2 C41.2 C42.2 C43.2 C44.2 C45.2 C46.2 C47.2 C51.2 C52.2 C56.2 C57.2 C59.2 J2.2 J2.3 J2.4 J2.5 Q5.2(S) R10.1 R15.1 R17.1 U2.22(FORCEON(GND)) U2.32(VSSIO) U2.43(VSSIO) U2.46(TESTMODE(GND)) U2.49(GND) U6.4(GND) U7.2(GND) U7.5(GND) X1.2(GND) Z1.2(GND) Z1.5(GND)
VDDBATT: C35.1 C42.1 R24.2 U2.47(VDDBATT) U7.1(OUT)
ANTENNA: J2.1 Z1.1(UN-IN)
BAL_N: C12.2 Z1.3(BAL-OUT1)
BAL_P: C11.2 Z1.4(BAL-OUT2)
EXTON: R17.2 U2.21(EXTON) U6.2(EN)
RESET#: Q5.3(D) U2.27(RST#)
RF-CS#: U2.24(SPICS#) ; port DW1000.RF-CS#
RF-IRQ: U2.45(IRQ_/_GPIO8) ; port DW1000.RF-IRQ
RF-MISO: U2.40(SPIMISO) ; port DW1000.RF-MISO
RF-MOSI: U2.39(SPIMOSI) ; port DW1000.RF-MOSI
RF-RESET: Q5.1(G) ; port DW1000.RF-RESET
RF-SCLK: U2.41(SPICLK) ; port DW1000.RF-SCLK
RF-WAKE-UP: U2.23(WAKEUP) ; port DW1000.RF-WAKE-UP
RF_N: C12.1 U2.17(RF_N)
RF_P: C11.1 U2.16(RF_P)
VDDCLK: C1.2 C2.1 C8.2 U2.9(VDDCLK)
VDDIF: C29.1 U2.7(VDDIF)
VDDIO: C39.1 U2.31(VDDIO) U2.42(VDDIO)
VDDMS: C30.1 U2.6(VDDMS)
VDDREG: C36.1 C41.1 U2.20(VDDREG) U2.44(VDDDIG)
VDDSYN: C28.1 U2.10(VDDSYN)
VDDVCO: C3.1 C4.1 C5.1 U2.11(VDDVCO)
XTAL1: R7.1 U2.3(EXTCLK_/_XTAL1)
XTAL2: R16.1 U2.4(XTAL2)
NetC2_2: C2.2 R1.2
NetC4_2: C4.2 R2.1
NetC5_2: C5.2 R2.2 U2.12(VCOTUNE)
NetC6_2: C6.2 R7.2 X1.3(X2)
NetC7_2: C7.2 R16.2 X1.1(X1)
NetC8_1: C8.1 R1.1 U2.8(CLKTUNE)
NetL3_2: L3.2 R10.2 X1.4(GND)
NetR15_2: R15.2 U2.5(VREF)

Not connected (* = marked no-connect by the designer): U2 1(NC) 2(NC) 13(NC) 14(NC) 29(SYNC/GPIO7) 30(GPIO6/EXTRXE/SPIPOL) 33(GPIO5_/_EXTTXE_/_SPIPHA) 34(GPIO4_/_EXTPA) 35(GPIO3_/_TXLED) 36(GPIO2_/_RXLED) 37(GPIO1_/_SFDLED) 38(GPIO0_/_RXOKLED); Z1 6(NC)

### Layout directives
differential pair; rule Width Constraint [Pref Impedance = 81.45ohms    Min Impedance = 80.00ohms    Max Impedance = 82.00ohms]: BAL_N, BAL_P, RF_N, RF_P

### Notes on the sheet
- (near U2) decaWave RF
- (near U2) I
- H
- (near C39) A
- (near C44) C
- (near C10) D
- (near C43) E
- (near C45) F
- (near C47) G
- A
- NOTES
- B
- Place capacitor at pin 42.
- Place capacitor(s) close to DW1000 VDDBATT
- C
- Place capacitor(s) close to DW1000  VDDAON
- D
- Place capacitor(s) close to DW1000  VDDLNA
- E
- F
- Place capacitor(s) close to DW1000  VDDPA1
- G
- Place capacitor(s) close to DW1000  VDDPA2
- Place capacitor(s) close to DW1000  VDDIOA
- Switching Regulator
- (near R24) Linear Regulator
- (near R24) H
- I
- Extra passive components allow the use of TCXO.
  Configuration shown is for crystal.
  See datasheet for the selected TCXO to determine correct configuration.
  LDO can be populated and bypass removed when used with TCXO
- For optimal RF performance find layout reference documentation at http://www.decawave.com/
- (near C35) B
- This work is licensed under a
- Creative Commons Attribution 4.0 International License
- http://creativecommons.org/licenses/by/4.0

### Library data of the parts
C1 C3 C15 C28-C31 C34-C36 C39 C41 C44 C46 C47 C51 = C00136: as C16 on sheet sam4s-mpu9250
C2 = C00457: Ceramic Capacitor 0402 27pF NP0; Part Number: GRM1555C1H270GA01D; CPN: C00457; Rating: 50V; Tolerance: 2%; Category Letter: C
C4 = C00460: CAP CER 820pF 50V 2% NP0 0402; Part Number: GRM1555C1H821GA01D; CPN: C00460; Category Letter: C
C5 = C00459: CAP CER 18PF 50V 2% NP0 0402; Part Number: GRM1555C1H180GA01D; CPN: C00459; Category Letter: C
C6 C7 C11 C12 = C00461: CAP CER 12pF 50V 2% NP0 0402; Part Number: GRM1555C1H120GA01D; CPN: C00461; Category Letter: C
C8 = C00458: as C54 on sheet sam4s-mpu9250
C10 = C00137: Capacitor 10nF 25V Ceramic X7R 0402; Part Number: GRM155R71E103KA01D; CPN: C00137; Tolerance: +/-10%; Category Letter: C
C13 C14 = C00441: CAP CER 10PF 50V 5% NP0 0402; Part Number: GRM1555C1H100JA01D; CPN: C00441; Category Letter: C
C20 C52 = C00468: CAP CER 47UF 6.3V 20% X5R 0805; Part Number: CL21A476MQCLRNC; CPN: C00468; Category Letter: C
C25 C56 = C00213: as C9 on sheet sam4s-mpu9250
C42 = C00342: Capacitor 4.7uF 6.3V Ceramic X5R 20% 0402; Part Number: GRM155R60J475ME47D; CPN: C00342; Category Letter: C
C43 C45 = C00462: Ceramic Capacitor 0402 330pF NP0; Part Number: GRM1555C1H331GA01D; CPN: C00462; Rating: 50V; Tolerance: 2%; Category Letter: C
C57 = C00171: as C48 on sheet sam4s-mpu9250
C59 = C00431: as C32 on sheet sam4s-mpu9250
J2 = J01340: RF SMA End Launch Jack 0.062" Thick 0.31" Shaft; Value: 50 Ohm; Rating: 18GHz; Category Letter: J
L3 = L00272: FERRITE BEAD 600 OHM 0402; Part Number: BK1005HS601-T; CPN: L00272; Rating: 300mA; Category Letter: L
Q5 = Q00171: as Q3 on sheet sam4s-mpu9250
R1 = R00702: RES 16K OHM 1/16W 1% 0402 SMD; Part Number: ERJ-2RKF1602X; CPN: R00702; Rating: 1/10W; Tolerance: Â±1%; Title: RES 16K OHM 1/10W 1% 0402 SMD; Category Letter: R
R2 = R00703: RES 270 OHM 1/10W 1% 0402 SMD; Part Number: ERJ-2RKF2700X; CPN: R00703; Category Letter: R
R7 R10 R16 R24 = R00661: as R18 on sheet sam4s-mpu9250
R15 = R00704: as R14 on sheet sam4s-mpu9250
R17 = R00696: as R5 on sheet sam4s-mpu9250
U2 = U00956: Ultra Wideband low-power transceiver QFN48-6M0; Category Letter: U
U6 = U00987: DC/DC Converter 1.8V 600MA SMD; Category Letter: U
U7 = U_TCR2LN_SDFN4: CPN: U01156; Value: 3.0V; Rating: 150mA; Description: IC REG LDO 3V 0.2A SDFN4; Category Letter: U
X1 = X_XTAL4P2G_ECX-2236: CPN: X00130; Tolerance: Â±10ppm; Title: CRYSTAL 38.40 MHZ 10PF SMD 2.5X2mm; Category Letter: X
Z1 = Z00014: RF Balun 3.0-8.0GHz UWB SMD; CPN: Z00014; Category Letter: Z

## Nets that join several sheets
3V3: sam4s-mpu9250 (31 pins), dw1000 (21 pins)
5V0: sam4s-mpu9250 (5 pins), dw1000 (C59.1 U6.1)
GND: sam4s-mpu9250 (42 pins), dw1000 (49 pins)
RF-CS#: sam4s-mpu9250 (U1.20), dw1000 (U2.24)
RF-IRQ: sam4s-mpu9250 (U1.15 U1.36), dw1000 (U2.45)
RF-MISO: sam4s-mpu9250 (U1.19), dw1000 (U2.40)
RF-MOSI: sam4s-mpu9250 (U1.17), dw1000 (U2.39)
RF-RESET: sam4s-mpu9250 (U1.21), dw1000 (Q5.1)
RF-SCLK: sam4s-mpu9250 (U1.16), dw1000 (U2.41)
RF-WAKE-UP: sam4s-mpu9250 (U1.10), dw1000 (U2.23)

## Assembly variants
battery powered: not fitted C26 J1 R5 R8 R17 R19
usb powered: not fitted C26 J2 R5 R8 R17 R19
